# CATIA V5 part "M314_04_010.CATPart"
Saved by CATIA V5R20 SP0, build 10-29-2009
Part number: M314_04_010
Source: Unknown
Property "ARTICLENO": "M314-04-010"
Property "B": "35.000"
Property "BOMINFO": "M314-04-010"
Property "CODE": "M314-04-010"
Property "D": "8.000"
Property "FINALFORCE": "78.4 (8)"
Property "INITIALFORCE": "16.6 (1.7)"
Property "K": "20.000"
Property "L": "85.000"
Property "LINA": "M314-04-010"
Property "M": "M16x2.0"
Property "NB": "M314-04-010"
Property "NBSYN": "$CODE."
Property "NN": "M314-04"
Property "NT": "Spring Plunger"
Property "SUPPLIER": "CF"
Property "SW": "5.000"
Bounding box of the stored display mesh (mm): x -8 to 8, y 0 to 105, z -8 to 8
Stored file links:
  C:\Users\Utente\Desktop\3D files M314\M314_04_010.CATPart
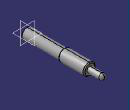
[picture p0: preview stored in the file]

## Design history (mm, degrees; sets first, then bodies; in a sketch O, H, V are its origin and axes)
Body1 "Geometry.1" (main body)
  Solid1 "M314_04_010.catpart": solid without history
